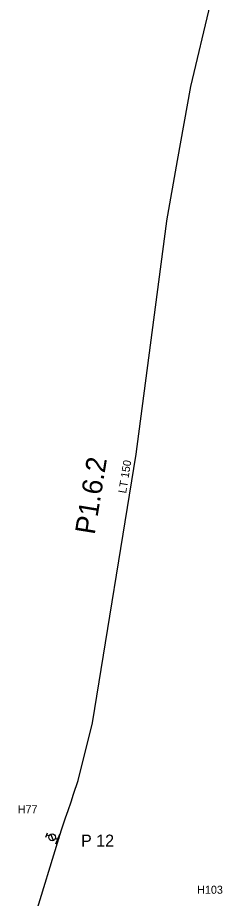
# Model space of a CAD drawing. Extents: x -569543 to -569081, y -1179531 to -1178244.
# Drawn here: x -569465.4 to -569414.2, y -1179107.6 to -1178887.5 of the extents above; entities that cross this region are included whole.
import ezdxf

# ---------------------------------------------------------------- set-up
doc = ezdxf.new("R2010")
doc.units = 0
for name, color, linetype in [('Vrstva 1', 7, 'Continuous'), ('Vrstva 19', 7, 'Continuous'), ('Vrstva 25', 7, 'Continuous'), ('Vrstva 29', 7, 'Continuous'), ('Vrstva 35', 7, 'Continuous')]:
    doc.layers.add(name, color=color, linetype=linetype)

# ---------------------------------------------------------------- blocks, each defined once
blk = doc.blocks.new('160')
at = {"layer": 'Vrstva 1'}
blk.add_circle((0, 0), 0.0458, dxfattribs=at)
blk = doc.blocks.new('133')
at = {"layer": 'Vrstva 1'}
for p, q in [((0.28, 0), (0, 0)), ((0.54, 0.58), (1.7, -0.58)), ((1.94, 0), (2.52, 0)), ((2.52, 0.58), (2.52, -0.58))]:
    blk.add_line(p, q, dxfattribs=at)
blk.add_circle((1.105, 0.003), 0.825, dxfattribs=at)
blk = doc.blocks.new('150')
at = {"layer": 'Vrstva 1'}
blk.add_line((0, 1.27), (0, -1.27), dxfattribs=at)

msp = doc.modelspace()

# ---------------------------------------------------------------- linework, layer by layer
at = {"layer": 'Vrstva 19'}
for points in [[(-569455.127, -1179092.557), (-569454.411, -1179090.428), (-569453.408, -1179087.448), (-569452.792, -1179085.617), (-569452.052, -1179083.419), (-569451.403, -1179081.488), (-569450.27, -1179078.122), (-569446.672, -1179063.686), (-569435.79, -1178996.58), (-569430.969, -1178959.864), (-569428.141, -1178938.321), (-569428.13, -1178938.26), (-569425.444, -1178923.169), (-569422.16, -1178904.72), (-569417.19, -1178884.05)], [(-569465.407, -1179126.447), (-569463.95, -1179120.5), (-569461.06, -1179111.92), (-569455.127, -1179092.557)]]:
    msp.add_lwpolyline(points, dxfattribs=at)
at = {"layer": 'Vrstva 25'}
msp.add_line((-569455.216, -1179092.848), (-569455.71, -1179092.71), dxfattribs=at)

# ---------------------------------------------------------------- block references
for name, p, xscale, yscale, rotation in [('133', (-569455.71, -1179092.71), 1.0365458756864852, 1.0365458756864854, 158.02850914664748), ('150', (-569455.463, -1179092.779), 1.035124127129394, 1.0351241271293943, -22.503654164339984)]:
    msp.add_blockref(name, p, dxfattribs=dict(at, xscale=xscale, yscale=yscale, rotation=rotation))
at = {"layer": 'Vrstva 29', "xscale": 1.0316957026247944, "yscale": 1.0316957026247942, "rotation": -23.584588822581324}
msp.add_blockref('160', (-569455.127, -1179092.557), dxfattribs=at)

# ---------------------------------------------------------------- texts
at = {"layer": 'Vrstva 25'}
for s, height, p in [('H77', 1.999992, (-569465.36, -1179086.29)), ('P 12', 2.999988, (-569449.56, -1179094.62)), ('H103', 1.999992, (-569420.513, -1179106.397))]:
    msp.add_text(s, height=height, dxfattribs=at).set_placement(p)
at = {"layer": 'Vrstva 35'}
for s, height, p in [('P1.6.2', 4.99998, (-569446.16, -1179016.818)), ('LT 150', 1.999992, (-569438.305, -1179006.439))]:
    msp.add_text(s, height=height, rotation=80.79, dxfattribs=at).set_placement(p)

doc.saveas('drawing.dxf')
